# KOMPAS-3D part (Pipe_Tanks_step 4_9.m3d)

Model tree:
1. X Axis
2. Y Axis
3. Z Axis  (labels: Pipe Dn 150; Bend 90 Dn 150)
     Òîëùèíà ñòåíêè 1 = 1

Referenced files in C:\Documents and Settings\kashirsky\Мои документы\Camtasia Studio\Pipelines3D\Tanks\: Tanks_step 4.a3d
Referenced files in C:\Program Files\ASCON\KOMPAS-3D V10\Libs\Piping\LOAD\: Piping_C_Pipe_150_1000.m3d
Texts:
  Pipe Dn 150
  Steel ASTM A295
  Three Point Plane
  Plane at Angle
  Line and Point Plane
  Axis through Two Vertices
  Axis of Feature
  Axis of Conical Surface
  Axis through Edge
  Trim by Surface
  Trim by Sketch
  Feature with No History
  Intersection Axis of Two Planes
  Two Line Plane
  Line and Face Plane
  Bend by line
  Hole in sheet body
  Cut in sheet body
  Point in CM
  Linear Dimension from Line to Point
  Surface Finish Symbol
  Geometric Tolerance Symbol
  Leader #1
  Leader #2
  Leader #3
  Shape Deviations and Datum
  Node point number
  Mark of coordination axis
  Node point designation
  Mark/Reference designation with leader
  Mark/reference designation on line
  Mark/Reference designation without leader
  Bend 90 Dn 150
  Plane of section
